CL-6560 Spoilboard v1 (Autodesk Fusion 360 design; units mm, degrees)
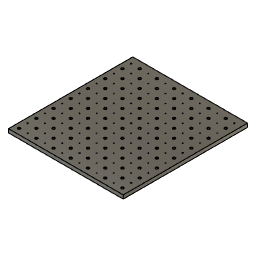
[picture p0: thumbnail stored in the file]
parameter "PlywoodThickness" = 19
sketch "Sketch1" plane through (0, 0, 0) normal (0, 0, 1) x axis (1, 0, 0)
  line L1 (300, 0) -> (-300, 0)
  line L2 (300, 650) -> (300, 0)
  line L3 (-300, 650) -> (300, 650)
  line L4 (-300, 0) -> (-300, 650)
  point P1 (0, 0)
  point P2 (-300, 0)
  point P3 (300, 0)
  point P5 (-300, 650)
  horizontal L1
  vertical L2
  horizontal L3
  vertical L4
  midpoint P1 L1
  dimension "d1" distance P2 P3 = 600
  dimension "d2" distance P2 P5 = 650
extrude "Extrude1" new body sketch "Sketch1" along normal blind 19 (= "PlywoodThickness")
sketch "Sketch2" plane through (0, 0, 19) normal (0, 0, 1) x axis (-1, 0, 0)
  line L1 (300, 0) -> (300, -650)
  line L2 (-300, 0) -> (300, 0)
  line L3 (-300, -650) -> (-300, 0)
  line L4 (300, -650) -> (-300, -650)
  line L5 (0, 0) -> (0, -650)
  line L6 (-300, -325) -> (300, -325)
  circle C1 centre (274, -30) radius 6.3
  circle C2 centre (229, -75) radius 6.3
  circle C3 centre (-266, -615) radius 2
  point P6 (0, -650)
  point P1 (0, 0)
  point P7 (0, 0)
  point P8 (300, -325)
  point P9 (-300, -325)
  point P10 (274, -30)
  point P12 (274, -30)
  point P11 (229, -75)
  point P25 (229, -75)
  point P193 (-266, -615)
  point P194 (-266, -615)
  midpoint L4 P6
  coincident P1 P7
  midpoint L1 P8
  midpoint L3 P9
  coincident P10 P12
  coincident P11 P25
  coincident P193 P194
  dimension "d11" diameter C1 = 12.6
  dimension "d33" diameter C2 = 12.6
  dimension "d58" distance L1 P12 = 26
  dimension "d59" distance L2 P12 = 30
  dimension "d100" diameter C3 = 4
  dimension "d62" R-Pattern1-uDistance = -45
  dimension "d63" R-Pattern1-vDistance = -45
extrude "Extrude8" cut sketch "Sketch2" profile of C3 against normal blind 0.5
rectangular_pattern "R-Pattern8" countU 13 CountV 14 uSpaceDistance 45 vSpaceDistance 45
extrude "Extrude2" cut sketch "Sketch2" profile of C1 C2 against normal blind 1
sketch "Sketch4" plane through (0, 0, 19) normal (0, 0, 1) x axis (-1, 0, 0)
  circle C1 centre (274, -30) radius 4.35
  circle C2 centre (274, -30) radius 6.3
  circle C3 centre (229, -75) radius 4.35
  circle C4 centre (229, -75) radius 6.3
  concentric C3 C4
  concentric C1 C2
  dimension "d22" diameter C1 = 8.7
  dimension "d36" diameter C3 = 8.7
extrude "Extrude3" cut sketch "Sketch4" profile of C1 C3 against normal blind 10
sketch "Sketch6" plane through (0, 0, 9) normal (0, 0, 1) x axis (-1, 0, 0)
  circle C1 centre (274, -30) radius 4.35
  circle C2 centre (274, -30) radius 3.4
  circle C3 centre (229, -75) radius 3.4
  circle C4 centre (229, -75) radius 6.3
  concentric C1 C2
  concentric C3 C4
  dimension "d25" diameter C2 = 6.8
  dimension "d37" diameter C3 = 6.8
extrude "Extrude4" cut sketch "Sketch6" profile of C2 C3 no distance stored
rectangular_pattern "R-Pattern4" uSpaceDistance 90 vSpaceDistance 90
rectangular_pattern "R-Pattern5" uSpaceDistance 90 vSpaceDistance 90
sketch "Sketch3" plane through (0, 0, 0) normal (0, 0, 1) x axis (1, 0, 0)
  circle C1 centre (-274, 75) radius 10
  point P2 (-274, 75)
  point P51 (-274, 75)
  coincident P2 P51
  dimension "d77" diameter C1 = 20
sketch "Sketch4" plane through (0, 0, 19) normal (0, 0, 1) x axis (-1, 0, 0)
  circle C1 centre (274, -75) radius 3.4
  circle C2 centre (274, -75) radius 2
  concentric C1 C2
  dimension "d89" diameter C1 = 6.8
extrude "Extrude7" cut sketch "Sketch4" no distance stored
rectangular_pattern "R-Pattern6" uSpaceDistance 270 vSpaceDistance 270
extrude "Extrude6" cut sketch "Sketch3" along normal blind 12
rectangular_pattern "R-Pattern7" uSpaceDistance 270 vSpaceDistance 270
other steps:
create_component "CreateComponent1"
